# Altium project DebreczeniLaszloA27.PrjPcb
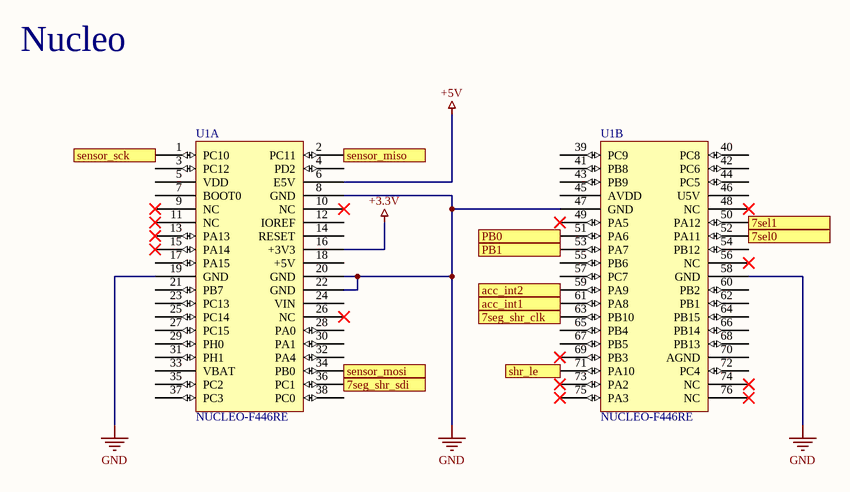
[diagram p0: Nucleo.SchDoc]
5 sheets, 31 parts. Net scope: flat (ports and power ports of the same name join across sheets).
Board file: hazi_kiindulas.PcbDoc
Sheets:
  Nucleo.SchDoc
  7segment.SchDoc
  Power.SchDoc
  Acceleration_module.SchDoc
  Pushbuttons.SchDoc

## Sheet Nucleo.SchDoc: Nucleo kártya
size A4; Author: Debreczeni László; Organization: BME-AUT; DocumentNumber: 1; Revision: A27; SheetNumber: 1; SheetTotal: 5

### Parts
U1  NUCLEO-F446RE  [FP_NUCLEO-64]  (parts A,B of 2)

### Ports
7seg_shr_clk (out), 7seg_shr_sdi (out), 7sel0 (out), 7sel1 (out), acc_int1 (in), acc_int2 (in), PB0 (in), PB1 (in), sensor_miso (in), sensor_mosi (out), sensor_sck (out), shr_le (out)

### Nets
+3.3V: U1.16(+3V3)
+5V: U1.6(E5V)
GND: U1.8(GND) U1.19(GND) U1.20(GND) U1.22(GND) U1.47(GND) U1.58(GND)
NetC4_2: U1.51(PA6) ; port PB0
NetC5_2: U1.53(PA7) ; port PB1
NetU1_1: U1.1(PC10) ; port sensor_sck
NetU1_2: U1.2(PC11) ; port sensor_miso
NetU1_34: U1.34(PB0) ; port sensor_mosi
NetU1_36: U1.36(PC1) ; port 7seg_shr_sdi
NetU1_50: U1.50(PA12) ; port 7sel1
NetU1_52: U1.52(PA11) ; port 7sel0
NetU1_59: U1.59(PA9) ; port acc_int2
NetU1_61: U1.61(PA8) ; port acc_int1
NetU1_63: U1.63(PB10) ; port 7seg_shr_clk
NetU1_71: U1.71(PA10) ; port shr_le

Not connected (* = marked no-connect by the designer): U1 3(PC12) 4(PD2) 5(VDD) 7(BOOT0) 9(NC)* 10(NC)* 11(NC)* 12(IOREF) 13(PA13)* 14(RESET) 15(PA14)* 17(PA15) 18(+5V) 21(PB7) 23(PC13) 24(VIN) 25(PC14) 26(NC)* 27(PC15) 28(PA0) 29(PH0) 30(PA1) 31(PH1) 32(PA4) 33(VBAT) 35(PC2) 37(PC3) 38(PC0) 39(PC9) 40(PC8) 41(PB8) 42(PC6) 43(PB9) 44(PC5) 45(AVDD) 46(U5V) 48(NC)* 49(PA5)* 54(PB12) 55(PB6) 56(NC)* 57(PC7) 60(PB2) 62(PB1) 64(PB15) 65(PB4) 66(PB14) 67(PB5) 68(PB13) 69(PB3)* 70(AGND) 72(PC4) 73(PA2)* 74(NC)* 75(PA3)* 76(NC)*

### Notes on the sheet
- Nucleo

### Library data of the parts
U1 = NUCLEO-F446RE: Reference: NUCLEO; Name: Nucleo F446RE

## Sheet 7segment.SchDoc: 7 szegmens kijelzők
size A4; Author: Debreczeni László; Organization: BME-AUT; DocumentNumber: 2; Revision: A27; SheetNumber: 2; SheetTotal: 5
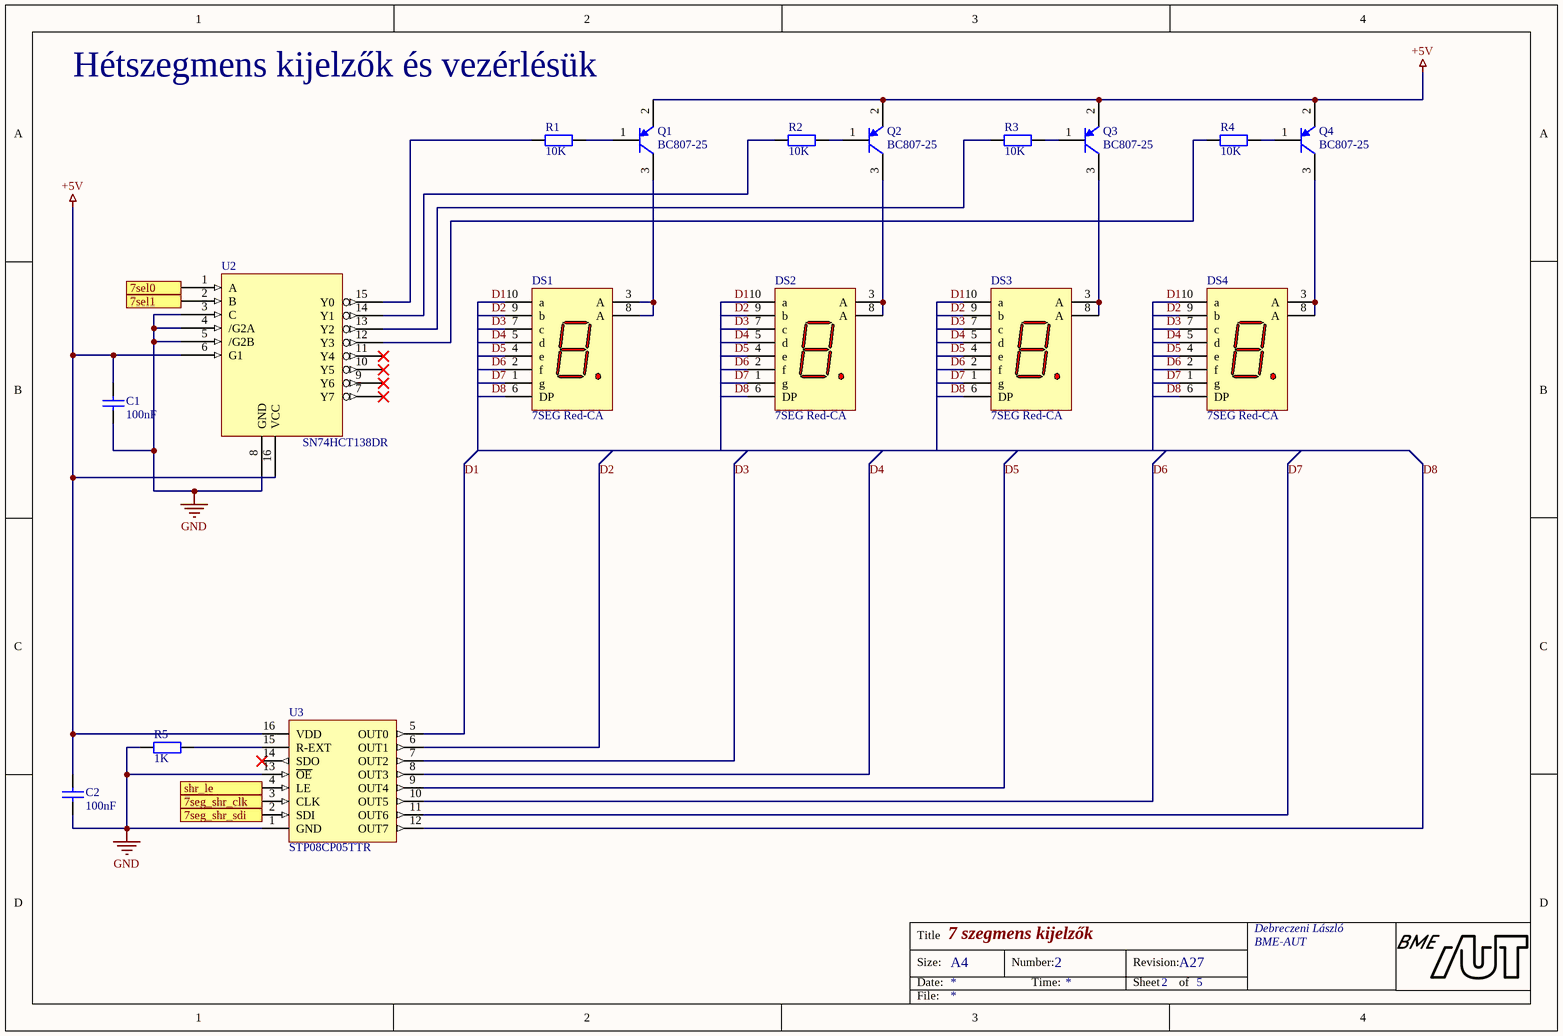
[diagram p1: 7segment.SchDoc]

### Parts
C1  100nF  [FP_1206_CAP_125]
C2  100nF  [FP_1206_CAP_125]
DS1  7SEG Red-CA  [FP_7SEG]
DS2  7SEG Red-CA  [FP_7SEG]
DS3  7SEG Red-CA  [FP_7SEG]
DS4  7SEG Red-CA  [FP_7SEG]
Q1  BC807-25  [SOT95P240X115-3M]
Q2  BC807-25  [SOT95P240X115-3M]
Q3  BC807-25  [SOT95P240X115-3M]
Q4  BC807-25  [SOT95P240X115-3M]
R1  10K  [FP_1206_RES]
R2  10K  [FP_1206_RES]
R3  10K  [FP_1206_RES]
R4  10K  [FP_1206_RES]
R5  1K  [FP_1206_RES]
U2  SN74HCT138DR  [SOIC127P600X175-16M]
U3  STP08CP05TTR  [TSOP65P640X120-16M]

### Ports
7seg_shr_clk (in), 7seg_shr_sdi (in), 7sel0 (in), 7sel1 (in), shr_le (in)

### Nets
+5V: C1.2 C2.2 Q1.2(E) Q2.2(E) Q3.2(E) Q4.2(E) U2.6(G1) U2.16(VCC) U3.16(VDD)
GND: C1.1 C2.1 R5.1 U2.3(C) U2.4(/G2A) U2.5(/G2B) U2.8(GND) U3.1(GND) U3.13(~{OE})
D1: DS1.10(a) DS2.10(a) DS3.10(a) DS4.10(a) U3.5(OUT0)
D2: DS1.9(b) DS2.9(b) DS3.9(b) DS4.9(b) U3.6(OUT1)
D3: DS1.7(c) DS2.7(c) DS3.7(c) DS4.7(c) U3.7(OUT2)
D4: DS1.5(d) DS2.5(d) DS3.5(d) DS4.5(d) U3.8(OUT3)
D5: DS1.4(e) DS2.4(e) DS3.4(e) DS4.4(e) U3.9(OUT4)
D6: DS1.2(f) DS2.2(f) DS3.2(f) DS4.2(f) U3.10(OUT5)
D7: DS1.1(g) DS2.1(g) DS3.1(g) DS4.1(g) U3.11(OUT6)
D8: DS1.6(DP) DS2.6(DP) DS3.6(DP) DS4.6(DP) U3.12(OUT7)
NetDS1_3: DS1.3(A) DS1.8(A) Q1.3(C)
NetDS2_3: DS2.3(A) DS2.8(A) Q2.3(C)
NetDS3_3: DS3.3(A) DS3.8(A) Q3.3(C)
NetDS4_3: DS4.3(A) DS4.8(A) Q4.3(C)
NetQ1_1: Q1.1(B) R1.2
NetQ2_1: Q2.1(B) R2.2
NetQ3_1: Q3.1(B) R3.2
NetQ4_1: Q4.1(B) R4.2
NetR1_1: R1.1 U2.15(Y0)
NetR2_1: R2.1 U2.14(Y1)
NetR3_1: R3.1 U2.13(Y2)
NetR4_1: R4.1 U2.12(Y3)
NetR5_2: R5.2 U3.15(R-EXT)
NetU1_36: U3.2(SDI) ; port 7seg_shr_sdi
NetU1_50: U2.2(B) ; port 7sel1
NetU1_52: U2.1(A) ; port 7sel0
NetU1_63: U3.3(CLK) ; port 7seg_shr_clk
NetU1_71: U3.4(LE) ; port shr_le

Not connected (* = marked no-connect by the designer): U2 7(Y7)* 9(Y6)* 10(Y5)* 11(Y4)*; U3 14(SDO)*

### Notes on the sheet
- Hétszegmens kijelzők és vezérlésük

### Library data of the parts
C1 C2 = CAP: Capacitor; Tolerance: 10%; Voltage: 50V; Name: 100nF 1206 Capacitor
DS1-DS4 = 7SEG Red-CA: 7-Segment Display: CA, RH DP; MinimumIntensity: 360 ucd; Note: IF = 5 mA; Colour: High Efficiency Red (HER); Note: Pins 1 and 6 are redundant Anodes.; Name: FYS-3911BUHR-21
Q1-Q4 = BC807-25: PNP General-purpose Transistor
R1-R4 = RES: Resistor; Tolerance: 5%; Power: 0.25W; Name: 10K 1206 Resistor
R5 = RES: Resistor; Tolerance: 5%; Power: 0.25W; Name: 1K 1206 Resistor
U2 = SN74HCT138DR: 3-line to 8-line decoder
U3 = STP08CP05TTR: Low voltage, low current power 8-bit shift register

## Sheet Power.SchDoc: Tápellátás
size A4; Author: Debreczeni László; Organization: BME-AUT; DocumentNumber: 3; Revision: A27; SheetNumber: 3; SheetTotal: 5
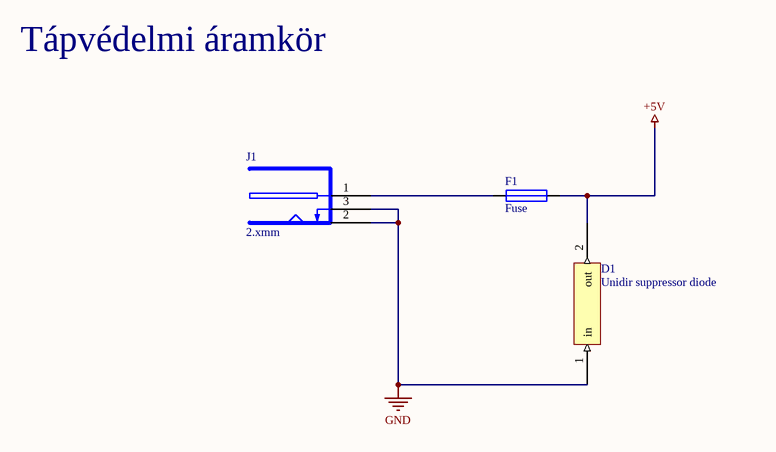
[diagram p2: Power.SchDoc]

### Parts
D1  Unidir suppressor diode  [DIOM4426X23M]
F1  Fuse  [FP_MULTIFUSE]
J1  2.xmm  [FP_DC_TAP_ANYA]

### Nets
+5V: D1.2(out) F1.2
GND: D1.1(in) J1.2(SLEEVE) J1.3(BREAK)
NetF1_1: F1.1 J1.1(PIN)

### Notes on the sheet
- Tápvédelmi áramkör

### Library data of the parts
D1 = Suppressor diode: Suppressor diode for transients
F1 = Fuse: Name: SMD Fuse
J1 = DC_TAP_ANYA: 2.xmm DC HEBA25 TÁPFESZÜLTSÉG ALJZAT ZÁRT, NYÁKBA 90°; Name: TÁP DC ANYA 5.5/2.1/9.5mm DCS-5521-5

## Sheet Acceleration_module.SchDoc: Gyorsulásérzékelő modul
size A4; Author: Debreczeni László; Organization: BME-AUT; DocumentNumber: 4; Revision: A27; SheetNumber: 4; SheetTotal: 5
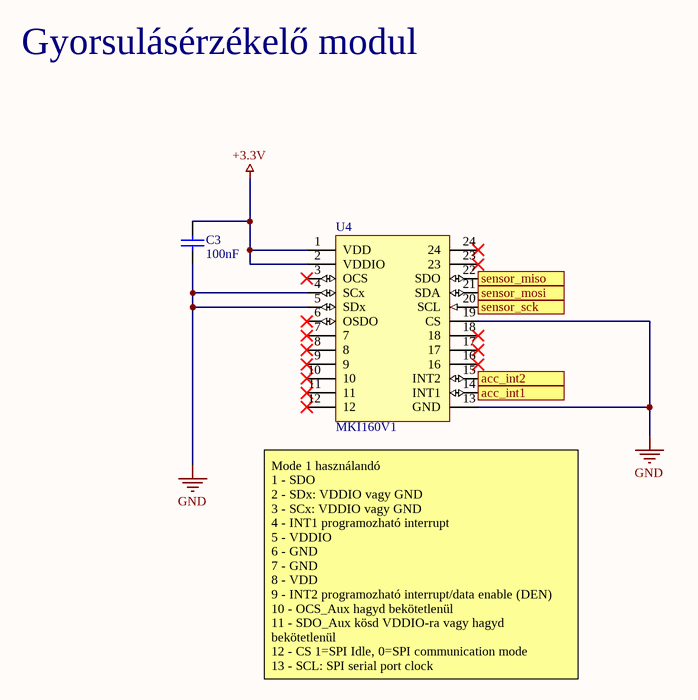
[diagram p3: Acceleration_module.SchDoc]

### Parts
C3  100nF  [FP_1206_CAP_125]
U4  MKI160V1  [FP_DIL24]

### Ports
acc_int1 (out), acc_int2 (out), sensor_miso (out), sensor_mosi (in), sensor_sck (in)

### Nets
+3.3V: C3.2 U4.1(VDD) U4.2(VDDIO)
GND: C3.1 U4.4(SCx) U4.5(SDx) U4.13(GND) U4.19(CS)
NetU1_1: U4.20(SCL) ; port sensor_sck
NetU1_2: U4.22(SDO) ; port sensor_miso
NetU1_34: U4.21(SDA) ; port sensor_mosi
NetU1_59: U4.15(INT2) ; port acc_int2
NetU1_61: U4.14(INT1) ; port acc_int1

Not connected (* = marked no-connect by the designer): U4 3(OCS)* 6(OSDO)* 7* 8* 9* 10* 11* 12* 16* 17* 18* 23* 24*

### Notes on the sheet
- Gyorsulásérzékelő modul
- (near U4) Mode 1 használandó
  1 - SDO
  2 - SDx: VDDIO vagy GND
  3 - SCx: VDDIO vagy GND
  4 - INT1 programozható interrupt
  5 - VDDIO
  6 - GND
  7 - GND
  8 - VDD
  9 - INT2 programozható interrupt/data enable (DEN)
  10 - OCS_Aux hagyd bekötetlenül
  11 - SDO_Aux kösd VDDIO-ra vagy hagyd bekötetlenül
  12 - CS 1=SPI Idle, 0=SPI communication mode
  13 - SCL: SPI serial port clock
  14 - SDA: SDI/3-wire interface SDO

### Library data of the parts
C3 = CAP: as C1 on sheet 7segment
U4 = MKI160V1: LSM6DS3 inertial module adapter; Name: MKI160V1 LSM6DS3 inertial module adapter; Reference: 511-STEVAL-MKI160V1

## Sheet Pushbuttons.SchDoc: Nyomógombok
size A4; Author: Debreczeni László; Organization: BME-AUT; DocumentNumber: 5; Revision: A27; SheetNumber: 5; SheetTotal: 5
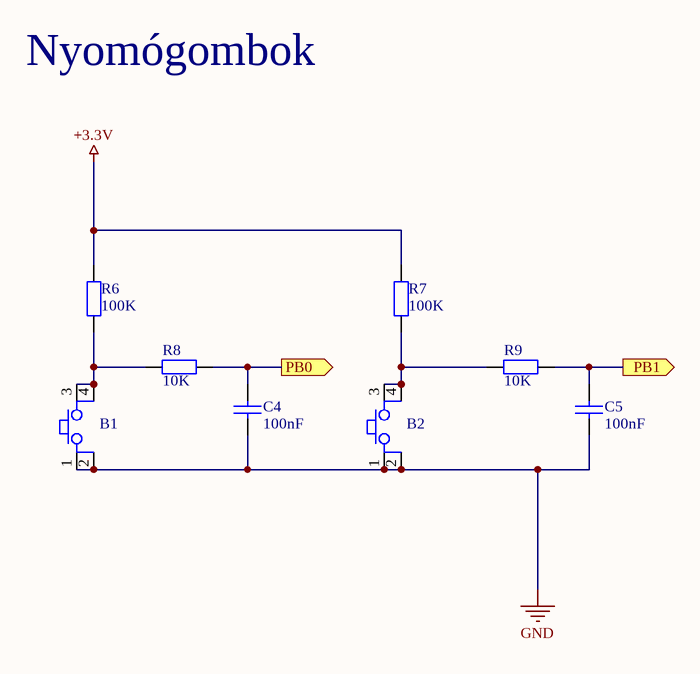
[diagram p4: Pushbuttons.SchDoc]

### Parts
B1  Button  [FP_BTN_SMD]  (value not drawn)
B2  Button  [FP_BTN_SMD]  (value not drawn)
C4  100nF  [FP_1206_CAP_125]
C5  100nF  [FP_1206_CAP_125]
R6  100K  [FP_1206_RES]
R7  100K  [FP_1206_RES]
R8  10K  [FP_1206_RES]
R9  10K  [FP_1206_RES]

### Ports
PB0 (out), PB1 (out)

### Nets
+3.3V: R6.2 R7.2
GND: B1.1 B1.2 B2.1 B2.2 C4.1 C5.1
NetB1_3: B1.3 B1.4 R6.1 R8.1
NetB2_3: B2.3 B2.4 R7.1 R9.1
NetC4_2: C4.2 R8.2 ; port PB0
NetC5_2: C5.2 R9.2 ; port PB1

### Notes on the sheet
- Nyomógombok

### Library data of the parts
B1 B2 = Button 4P: Push button; Name: 4P Pushbutton
C4 C5 = CAP: as C1 on sheet 7segment
R6 R7 = RES: Resistor; Tolerance: 5%; Power: 0.25W; Name: 100K 1206 resistor
R8 R9 = RES: as R1 on sheet 7segment

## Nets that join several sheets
+3.3V: Nucleo (U1.16), Acceleration_module (C3.2 U4.1 U4.2), Pushbuttons (R6.2 R7.2)
+5V: Nucleo (U1.6), 7segment (9 pins), Power (D1.2 F1.2)
GND: Nucleo (6 pins), 7segment (9 pins), Power (D1.1 J1.2 J1.3), Acceleration_module (5 pins), Pushbuttons (6 pins)
NetC4_2: Nucleo (U1.51), Pushbuttons (C4.2 R8.2)
NetC5_2: Nucleo (U1.53), Pushbuttons (C5.2 R9.2)
NetU1_1: Nucleo (U1.1), Acceleration_module (U4.20)
NetU1_2: Nucleo (U1.2), Acceleration_module (U4.22)
NetU1_34: Nucleo (U1.34), Acceleration_module (U4.21)
NetU1_36: Nucleo (U1.36), 7segment (U3.2)
NetU1_50: Nucleo (U1.50), 7segment (U2.2)
NetU1_52: Nucleo (U1.52), 7segment (U2.1)
NetU1_59: Nucleo (U1.59), Acceleration_module (U4.15)
NetU1_61: Nucleo (U1.61), Acceleration_module (U4.14)
NetU1_63: Nucleo (U1.63), 7segment (U3.3)
NetU1_71: Nucleo (U1.71), 7segment (U3.4)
